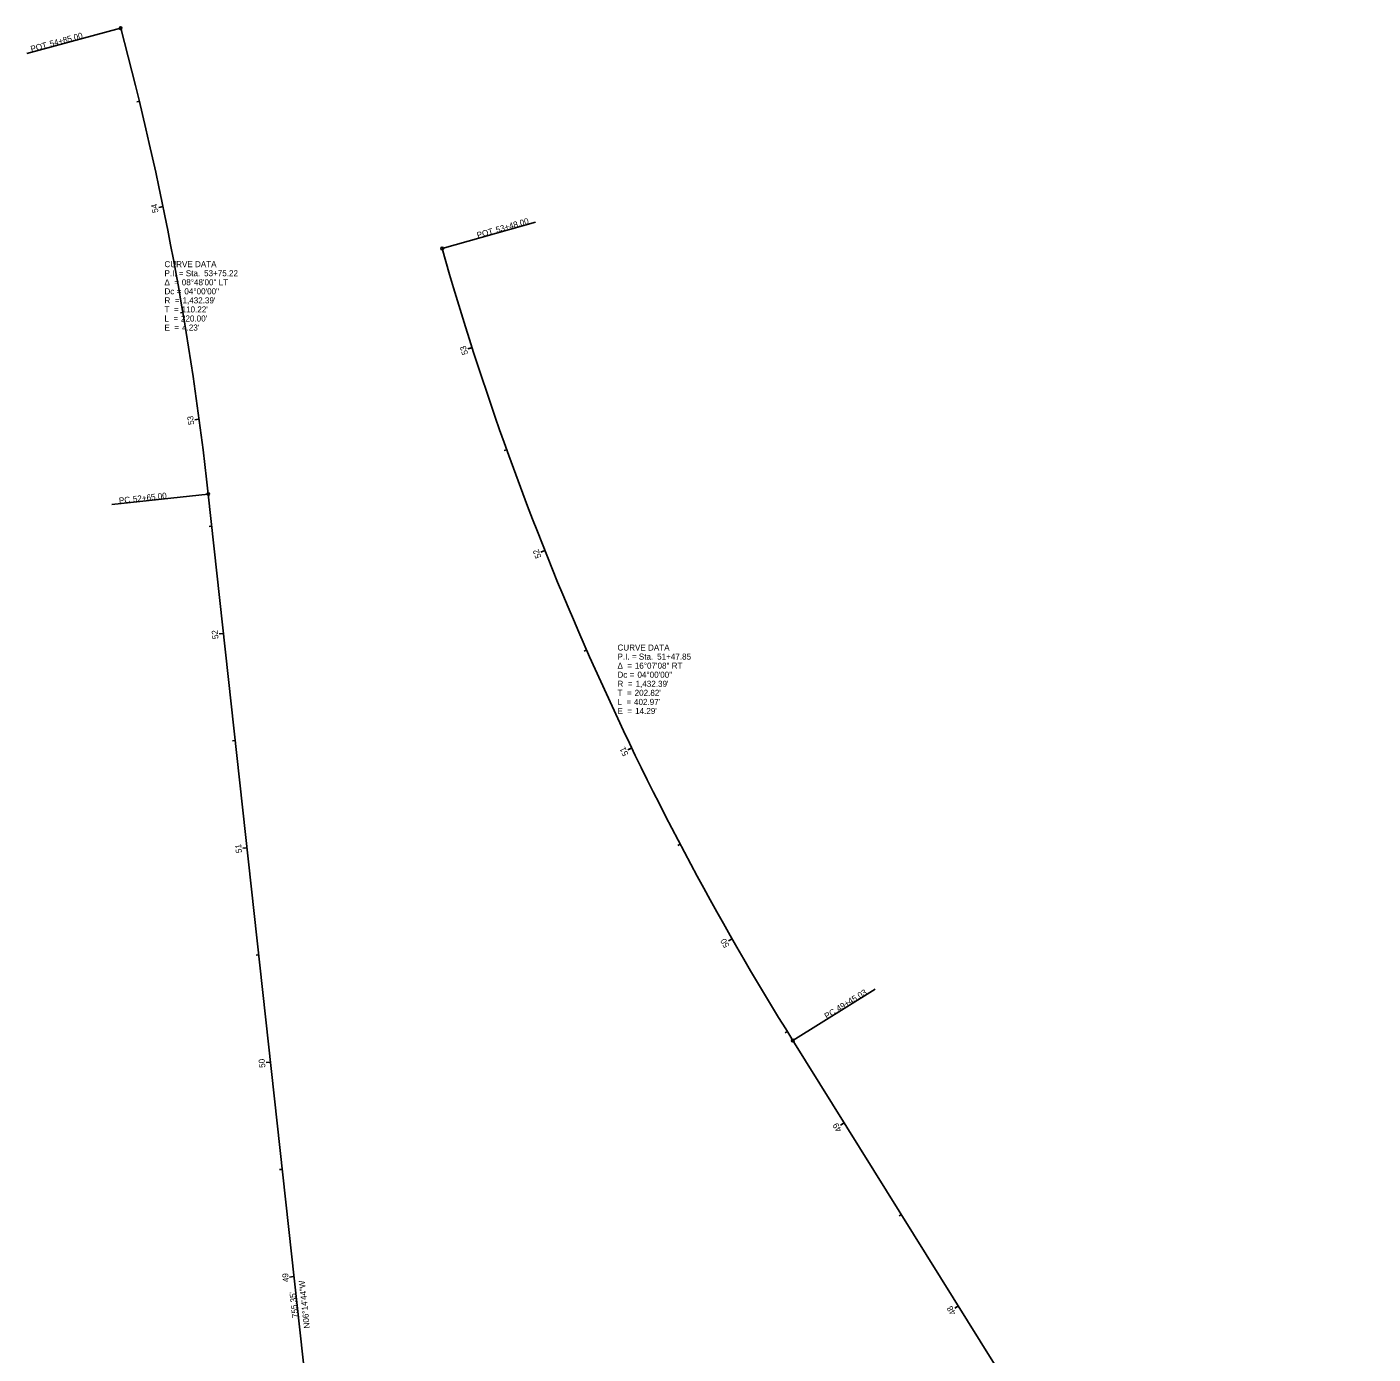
# Model space of a CAD drawing. Extents: x 1363001 to 1363920, y 487582 to 489802.
# Drawn here: x 1363001 to 1363625, y 489187 to 489802 of the extents above; entities that cross this region are included whole.
import ezdxf

# ---------------------------------------------------------------- set-up
doc = ezdxf.new("R2010")
doc.units = 0
for name, color, linetype in [('BR_X_SV_Beam_Seat', 7, 'Continuous'), ('BR_X_SV_Bottom_of_Beam_Text', 7, 'Continuous'), ('BR_X_SV_Shot_Marker', 7, 'Continuous'), ('DR_X_Cells', 7, 'Continuous'), ('DR_X_Elev_Flow', 7, 'Continuous'), ('PV_X_Curb', 7, 'Continuous'), ('RD_X_GR_Lt', 7, 'Continuous'), ('RD_X_GR_Rt', 7, 'Continuous'), ('SG_X_Interconnect_Cable', 7, 'Continuous'), ('SG_X_PullBox', 7, 'Continuous'), ('SV_P_Control_Cells_Set', 7, 'Continuous'), ('SV_X_Break_Lines', 7, 'Continuous'), ('SV_X_Shot_Marker', 7, 'Continuous'), ('SV_X_Text_Comment', 7, 'Continuous'), ('SV_X_Text_Name', 7, 'Continuous'), ('UT_X_Electric', 7, 'Continuous'), ('UT_X_Electric_Cells', 7, 'Continuous'), ('UT_X_Water', 7, 'Continuous')]:
    doc.layers.add(name, color=color, linetype=linetype)

msp = doc.modelspace()

# ---------------------------------------------------------------- linework, layer by layer
at = {"layer": 'BR_X_SV_Bottom_of_Beam_Text'}
for p, q in [((1363044.12, 489801.69), (1363000.67, 489790.01)), ((1363193.13, 489699.54), (1363236.42, 489711.81)), ((1363084.73, 489585.69), (1363039.99, 489580.79)), ((1363355.75, 489332.29), (1363393.94, 489356.1))]:
    msp.add_line(p, q, dxfattribs=at)
for centre in [(1363044.12, 489801.69), (1363193.13, 489699.54), (1363084.73, 489585.69), (1363355.75, 489332.29)]:
    msp.add_circle(centre, 0.6, dxfattribs=at)
at = {"layer": 'BR_X_SV_Shot_Marker'}
for p, q in [((1363052.8, 489767.78), (1363051.63, 489767.5)), ((1363063.74, 489719), (1363061.78, 489718.59)), ((1363072.98, 489669.86), (1363071.8, 489669.66)), ((1363206.99, 489653.59), (1363205.08, 489652.98)), ((1363080.49, 489620.43), (1363078.51, 489620.17)), ((1363223.06, 489606.24), (1363221.93, 489605.84)), ((1363086.36, 489570.78), (1363085.17, 489570.65)), ((1363240.77, 489559.49), (1363238.91, 489558.75)), ((1363091.8, 489521.07), (1363089.81, 489520.86)), ((1363260.1, 489513.38), (1363259, 489512.89)), ((1363097.24, 489471.37), (1363096.04, 489471.24)), ((1363281.02, 489467.97), (1363279.22, 489467.1)), ((1363102.68, 489421.67), (1363100.69, 489421.45)), ((1363303.52, 489423.32), (1363302.46, 489422.76)), ((1363327.57, 489379.49), (1363325.83, 489378.49)), ((1363108.12, 489371.97), (1363106.92, 489371.83)), ((1363353.13, 489336.52), (1363352.11, 489335.88)), ((1363113.56, 489322.26), (1363111.57, 489322.04)), ((1363379.58, 489294.08), (1363377.88, 489293.02)), ((1363119, 489272.56), (1363117.8, 489272.43)), ((1363406.03, 489251.65), (1363405.01, 489251.02)), ((1363124.44, 489222.86), (1363122.45, 489222.64)), ((1363432.48, 489209.23), (1363430.79, 489208.17))]:
    msp.add_line(p, q, dxfattribs=at)
at = {"layer": 'PV_X_Curb'}
for p, q in [((1363044.12, 489801.69), (1363000.67, 489790.01)), ((1363193.13, 489699.54), (1363236.42, 489711.81)), ((1363084.73, 489585.69), (1363039.99, 489580.79)), ((1363355.75, 489332.29), (1363393.94, 489356.1))]:
    msp.add_line(p, q, dxfattribs=at)
for centre in [(1363044.12, 489801.69), (1363193.13, 489699.54), (1363084.73, 489585.69), (1363355.75, 489332.29)]:
    msp.add_circle(centre, 0.6, dxfattribs=at)
at = {"layer": 'RD_X_GR_Rt'}
for p, q in [((1363327.57, 489379.49), (1363325.83, 489378.49)), ((1363113.56, 489322.26), (1363111.57, 489322.04))]:
    msp.add_line(p, q, dxfattribs=at)
at = {"layer": 'SG_X_PullBox'}
for p, q in [((1363063.74, 489719), (1363062.57, 489718.76)), ((1363206.99, 489653.59), (1363205.85, 489653.22)), ((1363080.49, 489620.43), (1363079.31, 489620.27)), ((1363240.77, 489559.49), (1363239.65, 489559.04)), ((1363091.8, 489521.07), (1363090.61, 489520.94)), ((1363281.02, 489467.97), (1363279.94, 489467.45)), ((1363102.68, 489421.67), (1363101.48, 489421.54)), ((1363327.57, 489379.49), (1363325.83, 489378.49)), ((1363113.56, 489322.26), (1363111.57, 489322.04)), ((1363379.58, 489294.08), (1363378.56, 489293.45)), ((1363124.44, 489222.86), (1363123.24, 489222.73)), ((1363432.48, 489209.23), (1363431.47, 489208.59))]:
    msp.add_line(p, q, dxfattribs=at)
at = {"layer": 'SV_X_Shot_Marker'}
msp.add_line((1363166.9, 488834.82), (1363084.73, 489585.69), dxfattribs=at)
for centre, start, end in [((1361660.84, 489429.86), 6.24567, 15.0457), ((1364571.23, 490090.15), 195.82502, 211.94387)]:
    msp.add_arc(centre, 1432.39, start, end, dxfattribs=at)
at = {"layer": 'SV_X_Text_Comment'}
for p, q in [((1363166.9, 488834.82), (1363084.73, 489585.69)), ((1363624.69, 488900.96), (1363355.75, 489332.29))]:
    msp.add_line(p, q, dxfattribs=at)
for centre, start, end in [((1361660.84, 489429.86), 6.24567, 15.0457), ((1364571.23, 490090.15), 195.82502, 211.94387)]:
    msp.add_arc(centre, 1432.39, start, end, dxfattribs=at)
at = {"layer": 'SV_X_Text_Name'}
for p, q in [((1363355.08, 489331.63), (1363356.42, 489332.96)), ((1363355.08, 489332.96), (1363356.42, 489331.63))]:
    msp.add_line(p, q, dxfattribs=at)
at = {"layer": 'UT_X_Water'}
for p, q in [((1363044.12, 489801.69), (1363000.67, 489790.01)), ((1363193.13, 489699.54), (1363236.42, 489711.81)), ((1363084.73, 489585.69), (1363039.99, 489580.79)), ((1363355.75, 489332.29), (1363393.94, 489356.1))]:
    msp.add_line(p, q, dxfattribs=at)
for centre in [(1363044.12, 489801.69), (1363193.13, 489699.54), (1363084.73, 489585.69), (1363355.75, 489332.29)]:
    msp.add_circle(centre, 0.6, dxfattribs=at)

# ---------------------------------------------------------------- texts
at = {"layer": 'BR_X_SV_Beam_Seat'}
msp.add_text('N06°14\'44"W', height=2.8, rotation=96.24567, dxfattribs=at).set_placement((1363131.88, 489198.98))
at = {"layer": 'BR_X_SV_Bottom_of_Beam_Text'}
for s, rotation, p in [('54+85.00', 15.0457, (1363011.6, 489793)), ('POT', 15.0457, (1363002.79, 489790.63)), ('POT', 15.82502, (1363209.67, 489704.28)), ('53+48.00', 15.82502, (1363218.45, 489706.77)), ('PC', 6.24567, (1363043.48, 489581.22)), ('52+65.00', 6.24567, (1363049.96, 489581.93)), ('49+45.03', 31.94387, (1363376.98, 489345.59)), ('PC', 31.94387, (1363371.45, 489342.14))]:
    msp.add_text(s, height=2.8, rotation=rotation, dxfattribs=at).set_placement(p)
at = {"layer": 'BR_X_SV_Shot_Marker'}
for s, rotation, p in [('54', 101.64568, (1363061.68, 489716.38)), ('53', 107.74502, (1363205.23, 489650.74)), ('53', 97.64567, (1363078.26, 489617.94)), ('52', 111.74504, (1363239.21, 489556.51)), ('52', 96.24567, (1363089.5, 489518.62)), ('51', 115.74505, (1363279.61, 489465.04)), ('51', 96.24567, (1363100.37, 489419.38)), ('50', 119.74506, (1363326.44, 489376.32)), ('50', 96.24567, (1363111.26, 489319.81)), ('49', 121.94387, (1363378.56, 489290.9)), ('49', 96.24567, (1363122.14, 489220.43)), ('48', 121.94387, (1363431.48, 489206.02))]:
    msp.add_text(s, height=2.8, rotation=rotation, dxfattribs=at).set_placement(p)
at = {"layer": 'DR_X_Cells'}
msp.add_text("755.35'", height=2.8, rotation=96.24567, dxfattribs=at).set_placement((1363126.47, 489203.8))
at = {"layer": 'DR_X_Elev_Flow'}
for s, p in [('CURVE DATA', (1363064.43, 489690.89)), ('Δ  = ', (1363064.43, 489682.49)), ('P.I. = Sta. ', (1363064.43, 489686.69)), ('08°48\'00" LT', (1363072.45, 489682.49)), ('53+75.22', (1363082.79, 489686.69)), ('Dc = ', (1363064.43, 489678.29)), ('04°00\'00"', (1363073.66, 489678.29)), ('T  = ', (1363064.43, 489669.89)), ('R  = ', (1363064.43, 489674.09)), ("110.22'", (1363072.36, 489669.89)), ("1,432.39'", (1363072.79, 489674.09)), ('L  = ', (1363064.43, 489665.69)), ("220.00'", (1363072.07, 489665.69)), ('E  = ', (1363064.43, 489661.49)), ("4.23'", (1363072.58, 489661.49)), ('CURVE DATA', (1363274.44, 489513.12)), ('P.I. = Sta. ', (1363274.44, 489508.92)), ('51+47.85', (1363292.81, 489508.92)), ('Δ  = ', (1363274.44, 489504.72)), ('Dc = ', (1363274.44, 489500.52)), ('16°07\'08" RT', (1363282.46, 489504.72)), ('04°00\'00"', (1363283.68, 489500.52)), ('R  = ', (1363274.44, 489496.32)), ("1,432.39'", (1363282.81, 489496.32)), ('T  = ', (1363274.44, 489492.12)), ('L  = ', (1363274.44, 489487.92)), ("402.97'", (1363282.09, 489487.92)), ("202.82'", (1363282.37, 489492.12)), ('E  = ', (1363274.44, 489483.72)), ("14.29'", (1363282.59, 489483.72))]:
    msp.add_text(s, height=2.8, dxfattribs=at).set_placement(p)
at = {"layer": 'PV_X_Curb'}
for s, rotation, p in [('54+85.00', 15.0457, (1363011.6, 489793)), ('POT', 15.0457, (1363002.79, 489790.63)), ('POT', 15.82502, (1363209.67, 489704.28)), ('53+48.00', 15.82502, (1363218.45, 489706.77)), ('PC', 6.24567, (1363043.48, 489581.22)), ('52+65.00', 6.24567, (1363049.96, 489581.93)), ('49+45.03', 31.94387, (1363376.98, 489345.59)), ('PC', 31.94387, (1363371.45, 489342.14))]:
    msp.add_text(s, height=2.8, rotation=rotation, dxfattribs=at).set_placement(p)
at = {"layer": 'RD_X_GR_Lt'}
msp.add_text("755.35'", height=2.8, rotation=96.24567, dxfattribs=at).set_placement((1363126.47, 489203.8))
at = {"layer": 'RD_X_GR_Rt'}
for rotation, p in [(119.74506, (1363326.44, 489376.32)), (96.24567, (1363111.26, 489319.81))]:
    msp.add_text('50', height=2.8, rotation=rotation, dxfattribs=at).set_placement(p)
at = {"layer": 'SG_X_Interconnect_Cable'}
msp.add_text('N06°14\'44"W', height=2.8, rotation=96.24567, dxfattribs=at).set_placement((1363131.88, 489198.98))
at = {"layer": 'SG_X_PullBox'}
for rotation, p in [(119.74506, (1363326.44, 489376.32)), (96.24567, (1363111.26, 489319.81))]:
    msp.add_text('50', height=2.8, rotation=rotation, dxfattribs=at).set_placement(p)
at = {"layer": 'SV_P_Control_Cells_Set'}
for s, p in [('CURVE DATA', (1363064.43, 489690.89)), ('Δ  = ', (1363064.43, 489682.49)), ('P.I. = Sta. ', (1363064.43, 489686.69)), ('08°48\'00" LT', (1363072.45, 489682.49)), ('53+75.22', (1363082.79, 489686.69)), ('Dc = ', (1363064.43, 489678.29)), ('04°00\'00"', (1363073.66, 489678.29)), ('T  = ', (1363064.43, 489669.89)), ('R  = ', (1363064.43, 489674.09)), ("110.22'", (1363072.36, 489669.89)), ("1,432.39'", (1363072.79, 489674.09)), ('L  = ', (1363064.43, 489665.69)), ("220.00'", (1363072.07, 489665.69)), ('E  = ', (1363064.43, 489661.49)), ("4.23'", (1363072.58, 489661.49)), ('CURVE DATA', (1363274.44, 489513.12)), ('P.I. = Sta. ', (1363274.44, 489508.92)), ('51+47.85', (1363292.81, 489508.92)), ('Δ  = ', (1363274.44, 489504.72)), ('Dc = ', (1363274.44, 489500.52)), ('16°07\'08" RT', (1363282.46, 489504.72)), ('04°00\'00"', (1363283.68, 489500.52)), ('R  = ', (1363274.44, 489496.32)), ("1,432.39'", (1363282.81, 489496.32)), ('T  = ', (1363274.44, 489492.12)), ('L  = ', (1363274.44, 489487.92)), ("402.97'", (1363282.09, 489487.92)), ("202.82'", (1363282.37, 489492.12)), ('E  = ', (1363274.44, 489483.72)), ("14.29'", (1363282.59, 489483.72))]:
    msp.add_text(s, height=2.8, dxfattribs=at).set_placement(p)
at = {"layer": 'SV_X_Break_Lines'}
msp.add_text("755.35'", height=2.8, rotation=96.24567, dxfattribs=at).set_placement((1363126.47, 489203.8))
at = {"layer": 'UT_X_Electric'}
for s, p in [('CURVE DATA', (1363064.43, 489690.89)), ('Δ  = ', (1363064.43, 489682.49)), ('P.I. = Sta. ', (1363064.43, 489686.69)), ('08°48\'00" LT', (1363072.45, 489682.49)), ('53+75.22', (1363082.79, 489686.69)), ('Dc = ', (1363064.43, 489678.29)), ('04°00\'00"', (1363073.66, 489678.29)), ('T  = ', (1363064.43, 489669.89)), ('R  = ', (1363064.43, 489674.09)), ("110.22'", (1363072.36, 489669.89)), ("1,432.39'", (1363072.79, 489674.09)), ('L  = ', (1363064.43, 489665.69)), ("220.00'", (1363072.07, 489665.69)), ('E  = ', (1363064.43, 489661.49)), ("4.23'", (1363072.58, 489661.49)), ('CURVE DATA', (1363274.44, 489513.12)), ('P.I. = Sta. ', (1363274.44, 489508.92)), ('51+47.85', (1363292.81, 489508.92)), ('Δ  = ', (1363274.44, 489504.72)), ('Dc = ', (1363274.44, 489500.52)), ('16°07\'08" RT', (1363282.46, 489504.72)), ('04°00\'00"', (1363283.68, 489500.52)), ('R  = ', (1363274.44, 489496.32)), ("1,432.39'", (1363282.81, 489496.32)), ('T  = ', (1363274.44, 489492.12)), ('L  = ', (1363274.44, 489487.92)), ("402.97'", (1363282.09, 489487.92)), ("202.82'", (1363282.37, 489492.12)), ('E  = ', (1363274.44, 489483.72)), ("14.29'", (1363282.59, 489483.72))]:
    msp.add_text(s, height=2.8, dxfattribs=at).set_placement(p)
at = {"layer": 'UT_X_Electric_Cells'}
msp.add_text('N06°14\'44"W', height=2.8, rotation=96.24567, dxfattribs=at).set_placement((1363131.88, 489198.98))
at = {"layer": 'UT_X_Water'}
for s, rotation, p in [('54+85.00', 15.0457, (1363011.6, 489793)), ('POT', 15.0457, (1363002.79, 489790.63)), ('POT', 15.82502, (1363209.67, 489704.28)), ('53+48.00', 15.82502, (1363218.45, 489706.77)), ('PC', 6.24567, (1363043.48, 489581.22)), ('52+65.00', 6.24567, (1363049.96, 489581.93)), ('49+45.03', 31.94387, (1363376.98, 489345.59)), ('PC', 31.94387, (1363371.45, 489342.14))]:
    msp.add_text(s, height=2.8, rotation=rotation, dxfattribs=at).set_placement(p)

doc.saveas('drawing.dxf')
